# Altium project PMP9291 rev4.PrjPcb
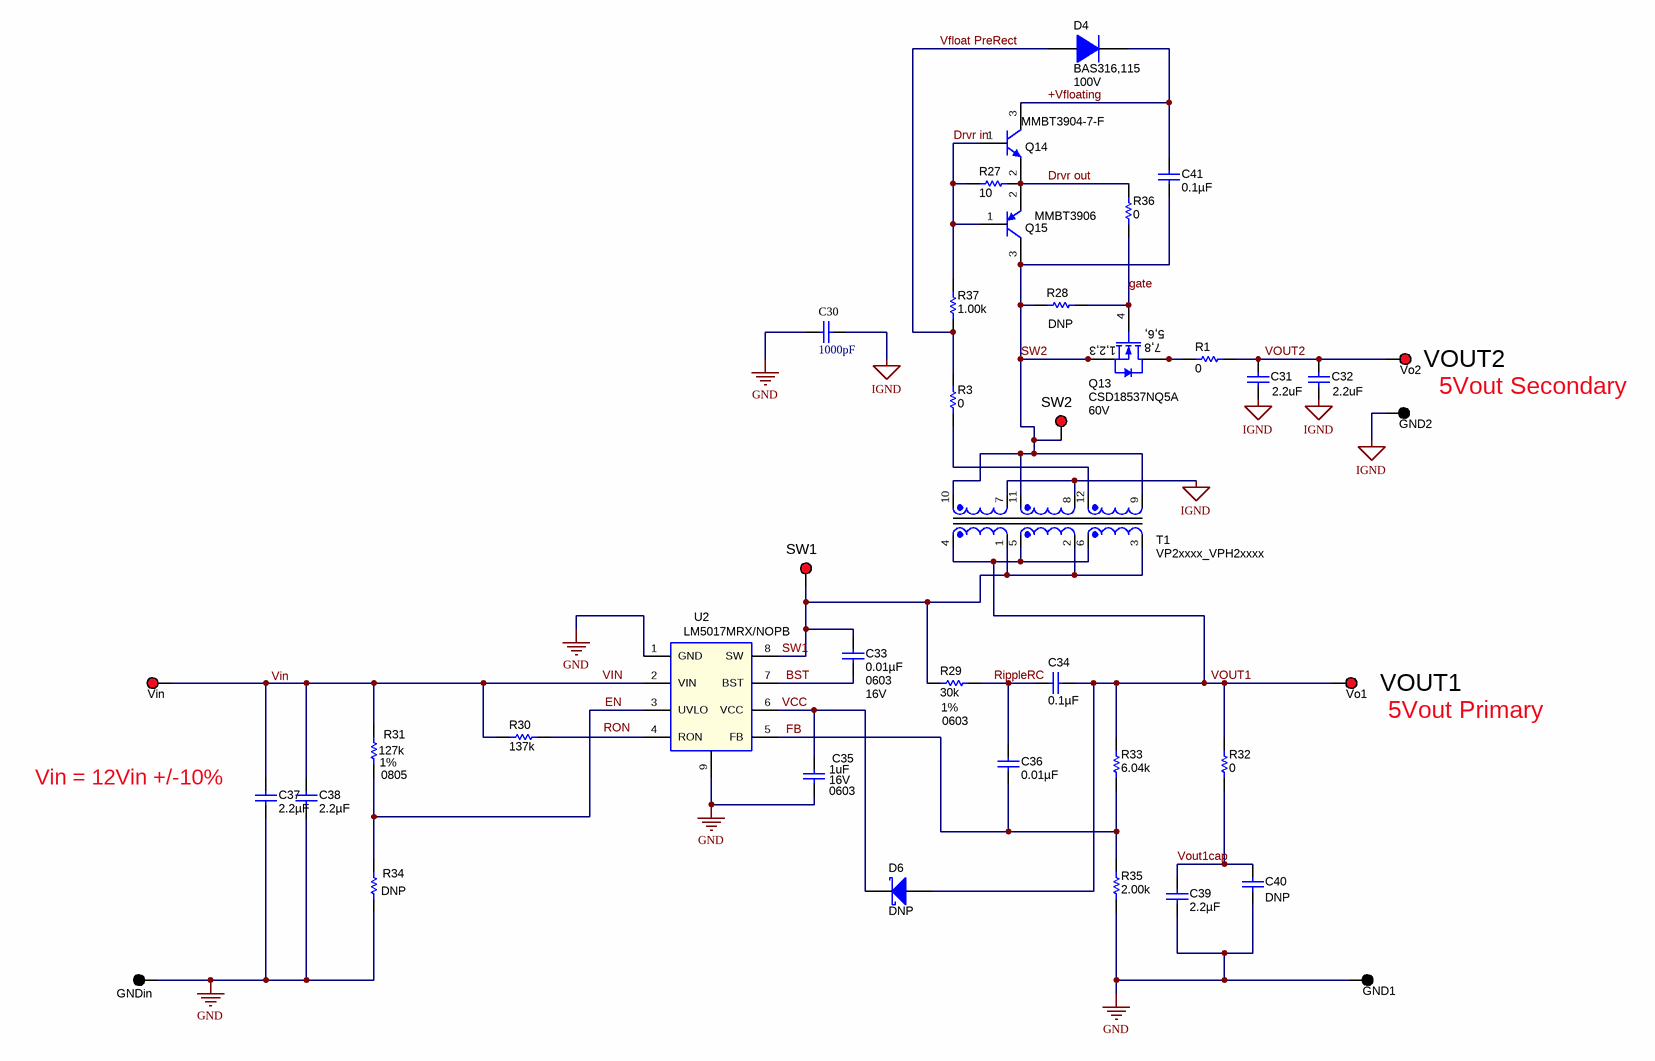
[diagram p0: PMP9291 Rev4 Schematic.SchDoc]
TID: PMP9291; TechSupport: http://www.ti.com/support; SCH_Rev: rev4; PRJ_Title: LM5017 Sync Flybuck; PRJ_Number: PMP9291; PRJ_Engineer: Hrag Kasparian; PRJ_Customer: Public Release; PCB_Rev: rev4; PCB_Layout: Hrag Kasparian; CopyrightYear: 2013
2 sheets, 57 parts. Net scope: global (net labels, ports and power ports of the same name join across sheets).
Board file: PMP9291 rev4.PcbDoc
Sheets:
  PMP9291 Rev4 Schematic.SchDoc
  PMP9291 rev4 Hardware_ANSI-B.SchDoc

## Sheet PMP9291 Rev4 Schematic.SchDoc
size 431 x 279 mm; DocumentNumber: 1; SheetNumber: 1; SheetTotal: 2; PageSetup: Record=PageOptions¦CenterHorizontal=True¦CenterVertical=True¦PrintScale=1.09¦XCorrection=1.00¦YCorrection=1.00¦PrintKind=1¦BorderSize=5000000¦LeftOffset=0¦BottomOffset=0¦Orientation=2¦PaperLength=1000¦PaperWidth=1000¦Scale=100¦PaperSource=15¦PrintQuality=600¦MediaType=1¦DitherType=10¦PaperKind=11x17¦PrintScaleMode=1

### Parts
C30  value 1000pF  [1808]  (hidden comment: VJ1210Y102KXGAT5Z)
C31  2.2uF  [0805_HV]
C32  2.2uF  [0805_HV]
C33  ValueDisplayed: 0.01µF  PackageReference: 0603  VDC_V: 16V  [0603_HV]  (hidden comment: GRM188R71C103KA01D)
C34  ValueDisplayed: 0.1µF  [0603_HV]  (hidden comment: 06035C104KAT2A)
C35  value 1uF  PackageReference: 0603  Value2: 16V  [0603_HV]  (hidden comment: C0603C105K4PACTU)
C36  ValueDisplayed: 0.01µF  [0603_HV]  (hidden comment: 06031C103JAT2A)
C37  ValueDisplayed: 2.2µF  [1206]  (hidden comment: GRM31CR61H225KA88L)
C38  ValueDisplayed: 2.2µF  [1206]  (hidden comment: GRM31CR61H225KA88L)
C39  ValueDisplayed: 2.2µF  [0805_HV]  (hidden comment: C2012X7R1C225K)
C40  DNP  [0603L]
C41  ValueDisplayed: 0.1µF  [0603]  (hidden comment: 06035C104KAT2A)
D4  BAS316,115  value 100V  [sod-323]
D6  DNP  [Diode_0603]
GND1  5001  [Keystone5001]  (value not drawn)
GND2  5001  [Keystone5001]  (value not drawn)
GNDin  5001  [Keystone5001]  (value not drawn)
Q13  CSD18537NQ5A  value 60V  [TRANS_NexFET_Q5A]
Q14  MMBT3904-7-F  [SOT-23]
Q15  MMBT3906  [SOT-23]
R1  value 0  [1206]  (hidden comment: CRCW12060000Z0EA)
R3  value 0  [0805_HV]  (hidden comment: CRCW08050000Z0EA)
R27  value 10  [0603_HV]  (hidden comment: CRCW060310R0JNEA)
R28  DNP  [0603_HV]
R29  value 30k  PackageReference: 0603  Value1: 1%  [0603_HV]  (hidden comment: CRCW060310K0FKEA)
R30  value 137k  [0603_HV]  (hidden comment: CRCW0603137KFKEA)
R31  value 127k  PackageReference: 0805  Value1: 1%  [0805_HV]  (hidden comment: CRCW0805127KFKEA)
R32  value 0  [1206]  (hidden comment: CRCW12060000Z0EA)
R33  value 6.04k  [0603_HV]  (hidden comment: CRCW06036K04FKEA)
R34  DNP  [0805_HV]
R35  value 2.00k  [0603_HV]  (hidden comment: CRCW06032K00FKEA)
R36  value 0  [0603_HV]  (hidden comment: CRCW060310R0JNEA)
R37  value 1.00k  [0603_HV]  (hidden comment: CRCW06031K00FKEA)
SW1  5000  [Keystone5000]  (value not drawn)
SW2  5000  [Keystone5000]  (value not drawn)
T1  VP2xxxx_VPH2xxxx  [VP2_VPH2]
U2  LM5017MRX/NOPB  [MRA08A_N]
Vin  5000  [Keystone5000]  (value not drawn)
Vo1  5000  [Keystone5000]  (value not drawn)
Vo2  5000  [Keystone5000]  (value not drawn)

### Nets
GND: C30.1 C35.2 C37.2 C38.2 C39.2 C40.2 GND1.1 GNDin.1 R34.1 R35.1 U2.1(GND) U2.9
IGND: C30.2 C31.2 C32.2 GND2.1 T1.7 T1.8
+Vfloating: C41.1 D4.1(K) Q14.3(C)
BST: C33.2 U2.7(BST)
Drvr in: Q14.1(B) Q15.1(B) R27.1 R37.2
Drvr out: Q14.2(E) Q15.2(E) R27.2 R36.2
EN: R31.1 R34.2 U2.3(UVLO)
FB: C36.2 R33.1 R35.2 U2.5(FB)
gate: Q13.4(G) R28.1 R36.1
RippleRC: C34.2 C36.1 R29.2
SW1: C33.1 R29.1 SW1.1 T1.1 T1.2 T1.3 U2.8(SW)
SW2: C41.2 Q13.1(S) Q13.2(S) Q13.3(S) Q15.3(C) R28.2 SW2.1 T1.9 T1.10 T1.11
VCC: C35.1 D6.1(K) U2.6(VCC)
Vfloat PreRect: D4.2(A) R3.2 R37.1
VIN: C37.1 C38.1 R30.1 R31.2 U2.2(VIN) Vin.1
VOUT1: C34.1 D6.2(A) R32.2 R33.2 T1.4 T1.5 T1.6 Vo1.1
Vout1cap: C39.1 C40.1 R32.1
VOUT2: C31.1 C32.1 R1.2 Vo2.1
NetQ13_5: Q13.5(D) Q13.6(D) Q13.7(D) Q13.8(D) Q13.9(D) R1.1
NetR3_1: R3.1 T1.12
NetR30_2: R30.2 U2.4(RON)

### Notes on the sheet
- VOUT2
- 5Vout Secondary
- (near Vo1) VOUT1
- (near Vo1) 5Vout Primary
- (near C37) Vin = 12Vin +/-10%
- Labels drawn without touching a wire or pin: RON, Vin

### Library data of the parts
C30 = VJ1210Y102KXGAT5Z: Ceramic, X7R, 1000V, 10%; Manufacturer: Vishay-Vitramon; Cap_Case: 1210; Polarized: N; TaMax_C: 125; TaMin_C: -55; Tolerance_%: 10; VDC_V: 1000; Cap_F: 1.0E-9; CompType: Capacitor; Value1: Ohm
C31 C32 = GRM21BR71E225KA73L: CAP, CERM, 2.2uF, 25V, +/-10%, X7R, 0805; Manufacturer: MuRata; Polarized: N; CompType: Capacitor; ValueDisplayed: DNP; U/M: EA; Cap_F: 0.0000022; Tolerance_%: 10; ESR_Ohm: 0.005; Value1: 0.005 ohm; VDC_V: 25; TaMin_C: -55; TaMax_C: 125; Cap_Case: 0805
C33 = GRM188R71C103KA01D: CAP, CERM, 0.01uF, 16V, +/-10%, X7R, 0603; Manufacturer: MuRata; Polarized: N; CompType: Capacitor; U/M: EA; Cap_F: 0.00000001; Tolerance_%: 10; TaMin_C: -55; TaMax_C: 125
C34 = 06035C104KAT2A: CAP, CERM, 0.1uF, 50V, +/-10%, X7R, 0603; Manufacturer: AVX; Polarized: N; CompType: Capacitor; U/M: EA; Cap_F: 0.0000001; Tolerance_%: 10; Value1: Unknown; VDC_V: 50; TaMin_C: -55; TaMax_C: 125; Cap_Case: 0603
C35 = C0603C105K4PACTU: CAP, CERM, 1uF, 16V, +/-10%, X5R, 0603; Manufacturer: Kemet; Polarized: N; TaMax_C: 85; TaMin_C: -55; Tolerance_%: 10; VDC_V: 16; Cap_F: 0.000001; CompType: Capacitor; ValueDisplayed: 1µF; U/M: EA
C36 = 06031C103JAT2A: CAP, CERM, 0.01uF, 100V, +/-5%, X7R, 0603; Manufacturer: AVX; Polarized: N; CompType: Capacitor; U/M: EA; Cap_F: 0.00000001; Tolerance_%: 5; ESR_Ohm: 0.098; Value1: 0.098 ohm; VDC_V: 100; TaMin_C: -55; TaMax_C: 125; Cap_Case: 0603
C37 C38 = GRM31CR61H225KA88L: CAP, CERM, 2.2uF, 50V, +/-10%, X5R, 1206; Manufacturer: MuRata; Polarized: N; CompType: Capacitor; U/M: EA; Cap_F: 0.0000022; Tolerance_%: 10; Value1: Unknown; VDC_V: 50; TaMin_C: -55; TaMax_C: 85
C39 = C2012X7R1C225K: CAP, CERM, 2.2uF, 16V, +/-10%, X7R, 0805; Manufacturer: TDK; Polarized: N; CompType: Capacitor; U/M: EA; Cap_F: 0.0000022; Tolerance_%: 10; ESR_Ohm: 0.0049; Value1: 0.0049 ohm; VDC_V: 16; TaMin_C: -55; TaMax_C: 125; Cap_Case: 0805
C40 = GRM21BR71E225KA73L: CAP, CERM, 2.2uF, 25V, +/-10%, X7R, 0805; Manufacturer: MuRata; Polarized: N; CompType: Capacitor; U/M: EA; Cap_F: 0.0000022; Tolerance_%: 10; ESR_Ohm: 0.005; Value1: 0.005 ohm; VDC_V: 25; TaMin_C: -55; TaMax_C: 125; Cap_Case: 0805
C41 = 06035C104KAT2A: CAP, CERM, 0.1uF, 50V, +/-10%, X7R, 0603; Manufacturer: AVX; Polarized: N; CompType: Capacitor; U/M: EA; Cap_F: 0.0000001; Tolerance_%: 10; Value1: Unknown; VDC_V: 50; TaMin_C: -55; TaMax_C: 125
D4 = BAS316,115: Diode, Ultrafast, 100V, 0.25A, SOD-323; Manufacturer: NXP Semiconductor; U/M: EA; Vf_V: 1.4; Value2: 1.4V; Io_A: 0.25; Vr_V: 100; TJmax_C: 150
D6 = CD0603-B0240: Diode, Schottky, 45V, 0.2A, 0603 Diode; Manufacturer: Bourns; Vf_V: 0.55; Io_A: 0.2; Vr_V: 45; TJmax_C: 125; U/M: EA; Value2: 0.55V
GND1 GND2 GNDin = 5001: Test Point, TH, Miniature, Black; Manufacturer: Keystone; CompType: Test Point Loop; U/M: EA
Q13 = CSD18537NQ5A: MOSFET, N-CH, 60V, 50A, SON 5x6mm; Manufacturer: Texas Instruments; Alternate Manufacturer: None; U/M: EA; ChType: N; VdsMax_V: 60; Value1: 0.036 ohm; Rdson45_Ohm: 0.036; Value2: 14 nC; QgTyp_nC: 14; Vgs_V: 20; IdsMax_A: 50
Q14 = MMBT3904-7-F, Diodes Inc.: Transistor, NPN, 40V, 0.2A, SOT-23; CompType: BJT; PNP: 0; NPN: 1; Vceo_V: 40; Vcesat1_V: 0.2; Value: 0.2V; HfeMax: 400; TaMin_C: -55; TaMax_C: 150; U/M: EA
Q15 = MMBT3906, Fairchild Semiconductor: Transistor, PNP, 40V, 0.2A, SOT-23; CompType: BJT; PNP: 1; NPN: 0; Vceo_V: 40; Vcesat1_V: 0.25; Value: 0.25V; IcRated_A: 0.2; HfeMax: 300; TaMin_C: -55; TaMax_C: 150; U/M: EA
R1 R32 = CRCW12060000Z0EA: RES, 0 ohm, 5%, 0.25W, 1206; Manufacturer: Vishay-Dale; CompType: Resistor; Value_Code: 0000; Tolerance_%: 5; Power_W: 0.25; VDC_V: 200; TempCo: 200 ppm/C; EIA_Code: E24; U/M: EA
R3 = CRCW08050000Z0EA: RES, 0 ohm, 5%, 0.125W, 0805; Manufacturer: Vishay-Dale; CompType: Resistor; Value_Code: 0000; Tolerance_%: 5; Power_W: 0.125; VDC_V: 150; TempCo: 200 ppm/C; EIA_Code: E24; U/M: EA
R27 = CRCW060310R0JNEA: RES, 10 ohm, 5%, 0.1W, 0603; Manufacturer: Vishay-Dale; CompType: Resistor; Value_Code: 10R0; Tolerance_%: 5; Power_W: 0.1; VDC_V: 75; TempCo: 200 ppm/C; EIA_Code: E24; U/M: EA
R28 R35 = CRCW06032K00FKEA: RES, 2.00k ohm, 1%, 0.1W, 0603; Manufacturer: Vishay-Dale; CompType: Resistor; Res_ohm: 2000; Value_Code: 2k00; Tolerance_%: 1; Power_W: 0.1; VDC_V: 75; TempCo: 100 ppm/C; EIA_Code: E96; U/M: EA
R29 = CRCW060310K0FKEA: RES, 10.0k ohm, 1%, 0.1W, 0603; Manufacturer: Vishay-Dale; CompType: Resistor; Tolerance_%: 1; VDC_V: 75; Power_W: 0.1; Res_ohm: 10000; Value_Code: 10k0; EIA_Code: E96; TempCo: 100 ppm/C; U/M: EA
R30 = CRCW0603137KFKEA: RES, 137k ohm, 1%, 0.1W, 0603; Manufacturer: Vishay-Dale; CompType: Resistor; Res_ohm: 137000; Tolerance_%: 1; Power_W: 0.1; VDC_V: 75; TempCo: 100 ppm/C; EIA_Code: E96; U/M: EA
R31 = CRCW0805127KFKEA: RES, 127k ohm, 1%, 0.125W, 0805; Manufacturer: Vishay-Dale; CompType: Resistor; Tolerance_%: 1; VDC_V: 150; Power_W: 0.125; Res_Ohm: 127000; EIA_Code: E96; TempCo: 100 ppm/C; U/M: EA
R33 = CRCW06036K04FKEA: RES, 6.04k ohm, 1%, 0.1W, 0603; Manufacturer: Vishay-Dale; CompType: Resistor; Res_ohm: 6040; Value_Code: 6k04; Tolerance_%: 1; Power_W: 0.1; VDC_V: 75; TempCo: 100 ppm/C; EIA_Code: E96; U/M: EA
R34 = CRCW08058K25FKEA: RES, 8.25k ohm, 1%, 0.125W, 0805; Manufacturer: Vishay-Dale; CompType: Resistor; Tolerance_%: 1; VDC_V: 150; Power_W: 0.125; Res_Ohm: 8250; Value_Code: 8k25; EIA_Code: E96; TempCo: 100 ppm/C; U/M: EA
R36 = CRCW060310R0JNEA: RES, 10 ohm, 5%, 0.1W, 0603; Manufacturer: Vishay-Dale; CompType: Resistor; Res_ohm: 10; Value_Code: 10R0; Tolerance_%: 5; Power_W: 0.1; VDC_V: 75; TempCo: 200 ppm/C; EIA_Code: E24; U/M: EA
R37 = CRCW06031K00FKEA: RES, 1.00k ohm, 1%, 0.1W, 0603; Manufacturer: Vishay-Dale; CompType: Resistor; Res_ohm: 1000; Value_Code: 1k00; Tolerance_%: 1; Power_W: 0.1; VDC_V: 75; TempCo: 100 ppm/C; EIA_Code: E96; U/M: EA
SW1 SW2 Vin Vo1 Vo2 = 5000: Test Point, TH, Miniature, Red; Manufacturer: Keystone; CompType: Test Point Loop; U/M: EA
T1 = VP2_VPH2: 1:1:1:1:1:1 Turns Ratio Versatile Transformers; Manufacturer: Cooper Bussmann Coiltronics; SymbolCreator: a0224881; CompType: Used in some BOM reports.  Useful for finding later.; U/M: EA, IN, or GM
U2 = LM5017MRX/NOPB: 100V, 600mA Constant On-Time Synchronous Buck Regulator, DDA0008B; Manufacturer: Texas Instruments; Alternate PartNumber: LM5017MR/NOPB; SymbolCreator: a0412235; CompType: IC; U/M: EA

## Sheet PMP9291 rev4 Hardware_ANSI-B.SchDoc
size 431 x 279 mm; Date: Not shown in title block; ApprovedBy: Not shown in title block; CheckedBy: Not shown in title block; Author: Not shown in title block; CompanyName: Not shown in title block; Engineer: Not shown in title block; Organization: Not shown in title block; Address1: Not shown in title block; Address2: Not shown in title block; Address3: Not shown in title block; Address4: Not shown in title block; DocumentNumber: 2; Revision: Use project parameter SCH_Rev; SheetNumber: 2; SheetTotal: 2; PageSetup: Record=PageOptions¦CenterHorizontal=True¦CenterVertical=True¦PrintScale=1.00¦XCorrection=1.00¦YCorrection=1.00¦PrintKind=0¦BorderSize=5000000¦LeftOffset=0¦BottomOffset=0¦Orientation=2¦PaperLength=1000¦PaperWidth=1000¦Scale=100¦PaperSource=15¦PrintQuality=600¦MediaType=1¦DitherType=10¦PaperKind=Letter¦PrintScaleMode=1
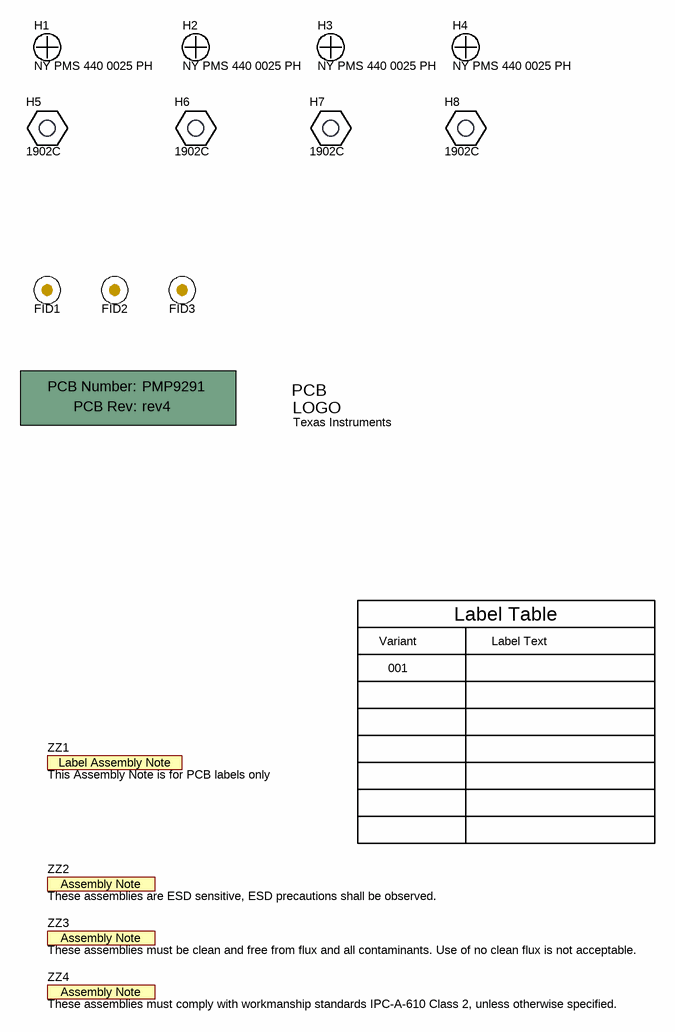
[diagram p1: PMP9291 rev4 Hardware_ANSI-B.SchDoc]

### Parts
!PCB  Printed Circuit Board  (value not drawn)  (mechanical)
FID1  Fiducial  [Fiducial10-20]  (value not drawn)
FID2  Fiducial  [Fiducial10-20]  (value not drawn)
FID3  Fiducial  [Fiducial10-20]  (value not drawn)
H1  NY PMS 440 0025 PH  [NY PMS 440 0025 PH]
H2  NY PMS 440 0025 PH  [NY PMS 440 0025 PH]
H3  NY PMS 440 0025 PH  [NY PMS 440 0025 PH]
H4  NY PMS 440 0025 PH  [NY PMS 440 0025 PH]
H5  1902C  [Keystone_1902C]
H6  1902C  [Keystone_1902C]
H7  1902C  [Keystone_1902C]
H8  1902C  [Keystone_1902C]
Logo1  Texas Instruments  [TI_Stacked_SolderMask_Small]  (no BOM)
ZZ1  This Assembly Note is for PCB labels only  [AssemblyNoteLabel]  (no BOM)
ZZ2  These assemblies are ESD sensitive, ESD precautions shall be observed.  [AssemblyNote]  (no BOM)
ZZ3  These assemblies must be clean and free from flux and all contaminants. Use of no clean flux is not acceptable.  [AssemblyNote]  (no BOM)
ZZ4  These assemblies must comply with workmanship standards IPC-A-610 Class 2, unless otherwise specified.  [AssemblyNote]  (no BOM)

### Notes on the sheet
- Variant
- Label Table
- Label Text
- 001

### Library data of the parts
!PCB = PCB: Manufacturer: Any; PartNumber: PMP9291; SymbolCreator: a0412235
FID1-FID3 = Fiducial: Fiducial mark.  There is nothing to buy or mount.; SymbolCreator: codlsc
H1-H4 = NY PMS 440 0025 PH: Machine Screw, Round, #4-40 x 1/4, Nylon, Philips panhead; Manufacturer: B&F Fastener Supply; CompType: Hardware; SymbolCreator: codlsc; U/M: EA
H5-H8 = 1902C: Standoff, Hex, 0.5"L #4-40 Nylon; Manufacturer: Keystone; CompType: Hardware
Logo1 = TI_Logo: Texas Instrument Corporate Signature; SymbolCreator: codlsc
ZZ1 = AssemblyNoteLabel: SymbolCreator: a0412235
ZZ2-ZZ4 = AssemblyNote: SymbolCreator: codlsc

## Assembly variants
001: not fitted C40 D6 FID1 FID2 FID3 R28 R34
